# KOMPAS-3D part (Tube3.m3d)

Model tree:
1. Plane XY
2. Plane ZX
3. Plane ZY
4. X Axis
5. Y Axis
6. Z Axis
7. Origin
8. Sketch:1
9. Extrude:1
     Wall Thickness 1 = 1; Wall Thickness 2 = 3; Distance 1 = 1000; Distance 2 = 10
10. Point:1
     X = 14400; Y = 2050; Z = 1000

Referenced files in D:\Documents and Settings\kashirsky\Рабочий стол\Seminar\: Cottage_balcony.a3d
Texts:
  Steel DIN 17102
  Three Point Plane
  Plane at Angle
  Line and Point Plane
  Axis through Two Vertices
  Axis of Feature
  Axis of Conical Surface
  Axis through Edge
  Trim by Surface
  Trim by Sketch
  Feature with No History
  Intersection Axis of Two Planes
  Two Line Plane
  Line and Face Plane
  Bend by line
  Hole in sheet body
  Cut in sheet body
  Point in CM
  Linear Dimension from Line to Point
  Surface Finish Symbol
  Geometric Tolerance Symbol
  Leader #1
  Leader #2
  Leader #3
  Shape Deviations and Datum
  Node point number
  Mark of coordination axis
  Node point designation
  Mark/Reference designation with leader
  Mark/reference designation on line
  Mark/Reference designation without leader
